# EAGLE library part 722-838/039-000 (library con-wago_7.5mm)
Serie 722, Federleiste mit Verriegelungsklinken / Series 722, Female connector with locking levers Polzahl / Pole No.: 8 Farbe / Color: lichtgrau / light gray Stand: 01.01.2012. Die jeweils aktuellen Daten zu diesem Artikel finden Sie in unserem Produktkatalog, den Sie unter www.wago.com einsehen können. As of: 01/01/2012. Please find the newest data for this article in our product catalogue, which can be viewed under www.wago.com.
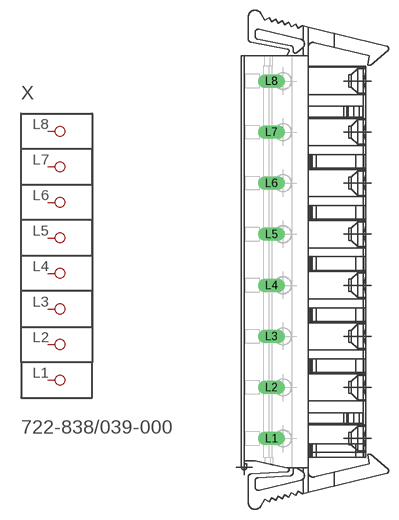
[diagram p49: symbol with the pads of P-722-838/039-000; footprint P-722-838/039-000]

Designator prefix X

## 722-838/039-000  [P-722-838/039-000]
L1  P1
L2  P2
L3  P3
L4  P4
L5  P5
L6  P6
L7  P7
L8  P8

## Footprint P-722-838/039-000 (pad centres in mm)
drill 1.3 long: L1 -6.018,-26.25; L2 -6.018,-18.75; L3 -6.018,-11.25; L4 -6.018,-3.75; L5 -6.018,3.75; L6 -6.018,11.25; L7 -6.018,18.75; L8 -6.018,26.25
